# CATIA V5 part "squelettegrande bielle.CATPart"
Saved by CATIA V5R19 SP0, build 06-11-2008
Part number: squelette grande bielle
Bounding box of the stored display mesh (mm): x 0 to 0, y 0 to 0, z -46 to -14
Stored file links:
  C:\Users\Gauthier\Documents\IFMA\IAO\TP2\squelettegrande bielle.CATPart
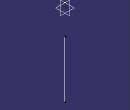
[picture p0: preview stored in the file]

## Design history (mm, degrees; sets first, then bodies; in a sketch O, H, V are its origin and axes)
Line1: type PtPt, SecondPoint Point3, FirstPoint Point2
Point1: stored without definition
Set1
  Point2: stored without definition
  Point3: stored without definition
Body1 (main body)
